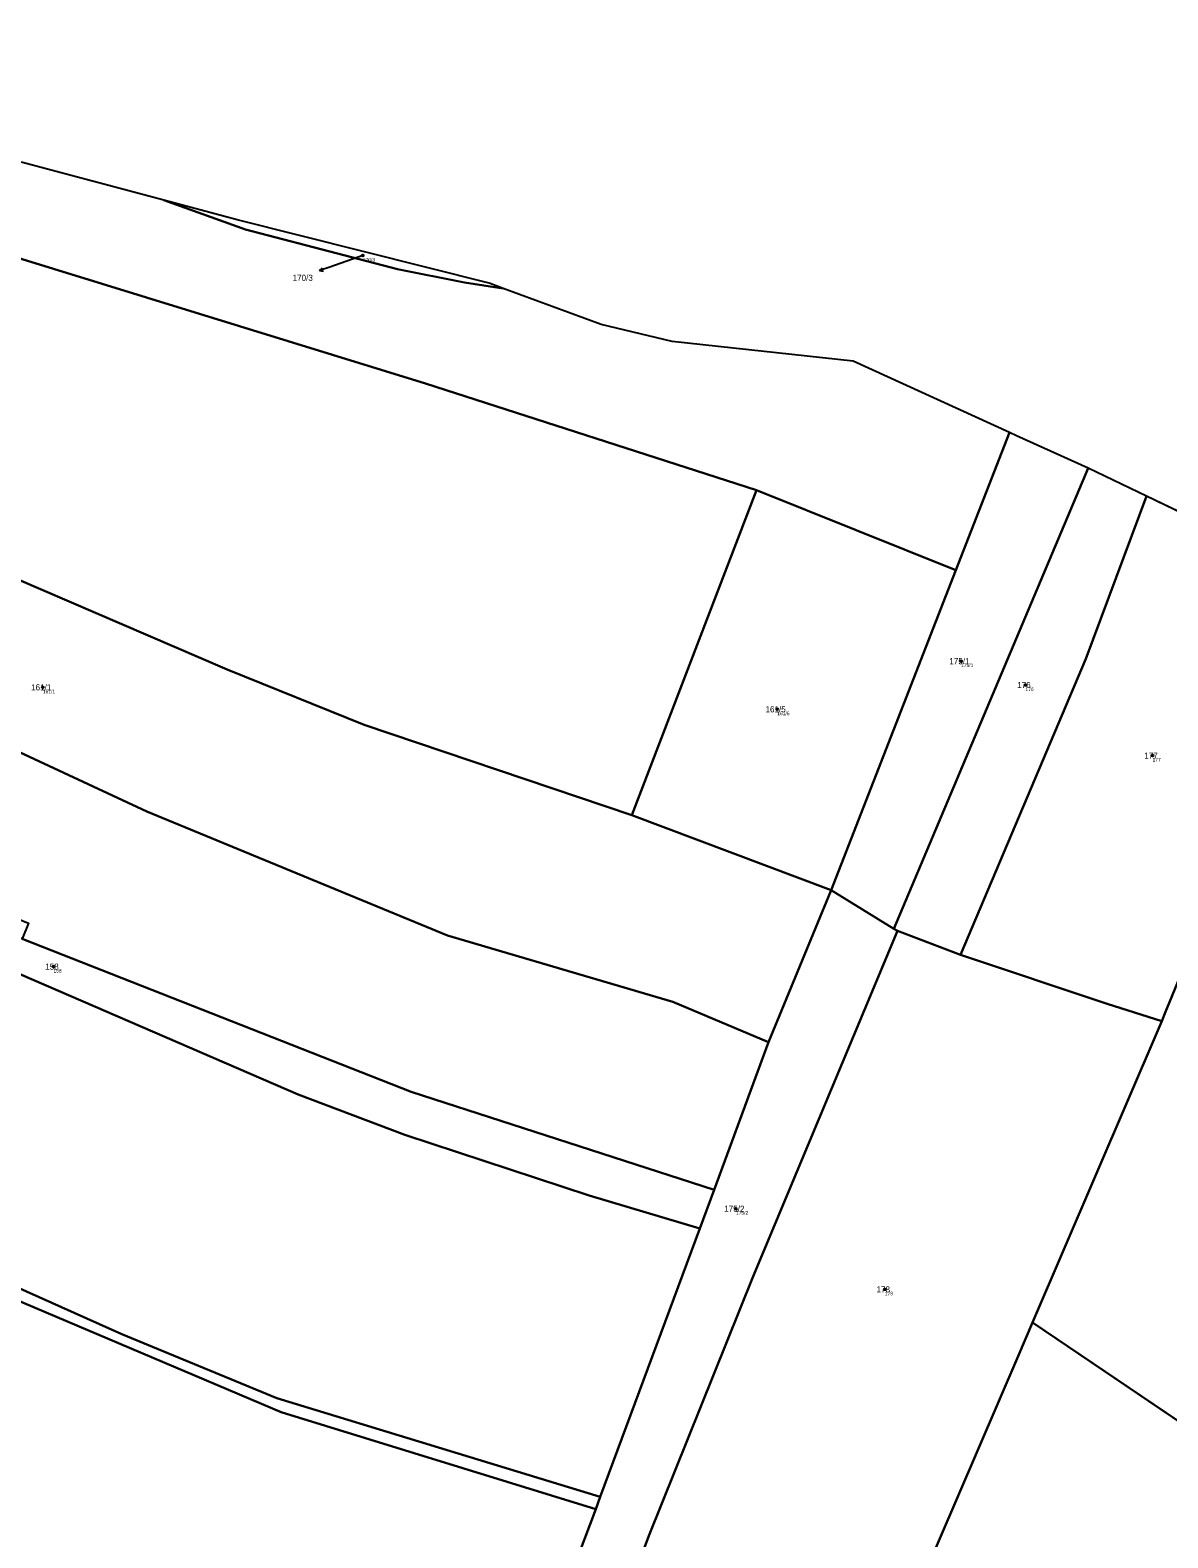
# Model space of a CAD drawing. Extents: x -700238 to -698499, y -1070626 to -1068006.
# Drawn here: x -699815.7 to -699496.9, y -1068498.7 to -1068076.1 of the extents above; entities that cross this region are included whole.
import ezdxf

# ---------------------------------------------------------------- set-up
doc = ezdxf.new("R2010")
doc.units = 0
for name, color, linetype in [('Definiční body', 7, 'Continuous'), ('Hranice parcel', 7, 'Continuous'), ('Parcelní čísla', 7, 'Continuous'), ('Polygon ku', 7, 'Continuous'), ('Polygon parcely', 7, 'Continuous'), ('Pop  PČ popisy', 7, 'Continuous')]:
    doc.layers.add(name, color=color, linetype=linetype)

msp = doc.modelspace()

# ---------------------------------------------------------------- linework, layer by layer
at = {"layer": 'Definiční body'}
for centre in [(-699722.47, -1068139.24994), (-699554.81, -1068252.94994), (-699812.13, -1068260.27994), (-699536.76, -1068259.63994), (-699606.32, -1068266.42994), (-699501.14, -1068279.40994), (-699809.15, -1068338.55994), (-699617.89, -1068406.41994), (-699576.18, -1068429.02994)]:
    msp.add_circle(centre, 0.25, dxfattribs=at)
at = {"layer": 'Hranice parcel'}
for p, q in [((-699778.25, -1068123.74), (-699818.2, -1068113.11)), ((-699757.69, -1068129.21), (-699778.25, -1068123.74)), ((-699687.02, -1068147.03), (-699757.69, -1068129.21)), ((-699683.1, -1068148.48), (-699687.02, -1068147.03)), ((-699655.7, -1068158.62), (-699683.1, -1068148.48)), ((-699635.75, -1068163.34), (-699655.7, -1068158.62)), ((-699585.07, -1068168.88), (-699635.75, -1068163.34)), ((-699541.2, -1068188.84), (-699585.07, -1068168.88)), ((-699556.25, -1068227.41), (-699541.2, -1068188.84)), ((-699539.23, -1068189.74), (-699541.2, -1068188.84)), ((-699519.18, -1068198.86), (-699539.23, -1068189.74)), ((-699573.62, -1068327.95), (-699519.18, -1068198.86)), ((-699502.86, -1068206.71), (-699519.18, -1068198.86)), ((-699647.05, -1068296.11), (-699612.1, -1068205.01)), ((-699556.25, -1068227.41), (-699612.1, -1068205.01)), ((-699468.76, -1068223.11), (-699502.86, -1068206.71)), ((-699591.24, -1068317.17), (-699556.25, -1068227.41)), ((-699591.24, -1068317.17), (-699647.05, -1068296.11)), ((-699608.73, -1068359.75), (-699591.24, -1068317.17)), ((-699591.24, -1068317.17), (-699573.62, -1068327.95)), ((-699572.66, -1068328.54), (-699573.62, -1068327.95)), ((-699572.66, -1068328.54), (-699554.94, -1068335.25)), ((-699499.35, -1068355.82), (-699534.75, -1068438.26)), ((-699498.53, -1068353.82), (-699499.35, -1068355.82)), ((-699623.95, -1068401.12), (-699608.73, -1068359.75)), ((-699627.99, -1068411.98), (-699623.95, -1068401.12)), ((-699655.97, -1068487.17), (-699627.99, -1068411.98)), ((-699534.75, -1068438.26), (-699459.74, -1068489.07)), ((-699657.18, -1068490.6), (-699655.97, -1068487.17)), ((-699671.14, -1068527.69), (-699657.18, -1068490.6))]:
    msp.add_line(p, q, dxfattribs=at)
for points in [[(-699612.1, -1068205.01), (-699704.91, -1068175.15), (-699847.75, -1068131.11), (-699903.56, -1068111.83), (-699936.42, -1068098.78), (-699978.4, -1068088.46), (-699998.31, -1068082.9)], [(-699647.05, -1068296.11), (-699722.11, -1068270.77), (-699760.47, -1068255.26), (-699834.34, -1068223.51), (-699836.42, -1068229.4), (-699946.86, -1068177.24), (-700044.14, -1068129.31), (-700087.38, -1068111.39)], [(-699778.25, -1068123.74), (-699755.33, -1068131.92), (-699712.7, -1068143.08), (-699693.92, -1068146.8), (-699683.1, -1068148.48)], [(-700091.82, -1068153.6), (-699982.79, -1068203.82), (-699863.89, -1068257.44), (-699783, -1068295.12), (-699698.72, -1068329.85), (-699635.57, -1068348.43), (-699608.73, -1068359.75)], [(-699554.94, -1068335.25), (-699519.85, -1068252.28), (-699502.86, -1068206.71)], [(-699627.99, -1068411.98), (-699659.02, -1068402.7), (-699710.69, -1068385.66), (-699740.56, -1068374.38), (-699875.66, -1068316.05), (-699927.93, -1068294.45), (-700000.63, -1068259.75), (-700062.96, -1068229.76), (-700089.79, -1068219.21)], [(-699446.94, -1068230.19), (-699466.45, -1068275.29), (-699484.18, -1068318.68), (-699496.38, -1068348.56), (-699497.48, -1068351.24), (-699498.53, -1068353.82)], [(-699623.95, -1068401.12), (-699708.94, -1068373.65), (-699817.93, -1068330.74)], [(-699655.01, -1068532.14), (-699642.31, -1068498.14), (-699613.14, -1068425.59), (-699572.66, -1068328.54)], [(-699554.94, -1068335.25), (-699513.83, -1068348.95), (-699498.53, -1068353.82)], [(-699655.97, -1068487.17), (-699746.59, -1068459.53), (-699790, -1068441.55), (-699866.66, -1068407.29), (-699955.8, -1068368.76), (-700005.69, -1068352.12), (-700047.78, -1068341.46)], [(-699657.18, -1068490.6), (-699745.37, -1068463.45), (-699826.68, -1068428.95), (-699890.63, -1068400.44), (-699955.93, -1068372.18), (-700009.61, -1068354.69), (-700046.18, -1068345.86)], [(-699583.54, -1068551.89), (-699538.81, -1068447.71), (-699534.75, -1068438.26)]]:
    msp.add_lwpolyline(points, dxfattribs=at)
at = {"layer": 'Polygon ku'}
for points in [[(-699468.76, -1068223.11), (-699502.86, -1068206.71), (-699519.18, -1068198.86), (-699539.23, -1068189.74), (-699541.2, -1068188.84), (-699585.07, -1068168.88), (-699635.75, -1068163.34), (-699655.7, -1068158.62), (-699683.1, -1068148.48), (-699687.02, -1068147.03), (-699757.69, -1068129.21), (-699778.25, -1068123.74), (-699818.2, -1068113.11)], [(-699459.74, -1068489.07), (-699534.75, -1068438.26), (-699499.35, -1068355.82), (-699498.53, -1068353.82), (-699497.48, -1068351.24), (-699496.38, -1068348.56)]]:
    msp.add_lwpolyline(points, dxfattribs=at)
at = {"layer": 'Polygon parcely'}
for points in [[(-699847.75, -1068131.11), (-699903.56, -1068111.83), (-699936.42, -1068098.78), (-699978.4, -1068088.46), (-699998.31, -1068082.9), (-699998.06, -1068112.08), (-700082.81, -1068076.08), (-700090.39, -1068110.64), (-700087.38, -1068111.39), (-700044.14, -1068129.31), (-699946.86, -1068177.24), (-699836.42, -1068229.4), (-699834.34, -1068223.51), (-699760.47, -1068255.26), (-699722.11, -1068270.77), (-699647.05, -1068296.11), (-699612.1, -1068205.01), (-699704.91, -1068175.15)], [(-699591.24, -1068317.17), (-699647.05, -1068296.11), (-699722.11, -1068270.77), (-699760.47, -1068255.26), (-699834.34, -1068223.51), (-699836.42, -1068229.4), (-699946.86, -1068177.24), (-700044.14, -1068129.31), (-700087.38, -1068111.39), (-700089.86, -1068130.36), (-700090.77, -1068136.56), (-700089.78, -1068150.52), (-700091.82, -1068153.6), (-699982.79, -1068203.82), (-699863.89, -1068257.44), (-699783, -1068295.12), (-699698.72, -1068329.85), (-699635.57, -1068348.43), (-699608.73, -1068359.75)], [(-699712.7, -1068143.08), (-699693.92, -1068146.8), (-699683.1, -1068148.48), (-699687.02, -1068147.03), (-699757.69, -1068129.21), (-699778.25, -1068123.74), (-699755.33, -1068131.92)], [(-699881.04, -1068299.73), (-699816.11, -1068326.4), (-699817.93, -1068330.74), (-699708.94, -1068373.65), (-699623.95, -1068401.12), (-699608.73, -1068359.75), (-699635.57, -1068348.43), (-699698.72, -1068329.85), (-699783, -1068295.12), (-699863.89, -1068257.44), (-699982.79, -1068203.82), (-700091.82, -1068153.6), (-700093.72, -1068156.82), (-700098.76, -1068159.5), (-700092.58, -1068198.68), (-699982.77, -1068250.43)], [(-699519.18, -1068198.86), (-699539.23, -1068189.74), (-699541.2, -1068188.84), (-699556.25, -1068227.41), (-699591.24, -1068317.17), (-699573.62, -1068327.95)], [(-699572.66, -1068328.54), (-699554.94, -1068335.25), (-699519.85, -1068252.28), (-699502.86, -1068206.71), (-699519.18, -1068198.86), (-699573.62, -1068327.95)], [(-699708.94, -1068373.65), (-699817.93, -1068330.74), (-699901.99, -1068293.89), (-700054.94, -1068220), (-700092.18, -1068203.16), (-700089.79, -1068219.21), (-700062.96, -1068229.76), (-700000.63, -1068259.75), (-699927.93, -1068294.45), (-699875.66, -1068316.05), (-699740.56, -1068374.38), (-699710.69, -1068385.66), (-699659.02, -1068402.7), (-699627.99, -1068411.98), (-699623.95, -1068401.12)], [(-699612.1, -1068205.01), (-699647.05, -1068296.11), (-699591.24, -1068317.17), (-699556.25, -1068227.41)], [(-699468.76, -1068223.11), (-699502.86, -1068206.71), (-699519.85, -1068252.28), (-699554.94, -1068335.25), (-699513.83, -1068348.95), (-699498.53, -1068353.82), (-699497.48, -1068351.24), (-699496.38, -1068348.56), (-699484.18, -1068318.68), (-699466.45, -1068275.29), (-699446.94, -1068230.19)], [(-700000.63, -1068259.75), (-700062.96, -1068229.76), (-700089.79, -1068219.21), (-700079.51, -1068265.19), (-700047.78, -1068341.46), (-700005.69, -1068352.12), (-699955.8, -1068368.76), (-699866.66, -1068407.29), (-699790, -1068441.55), (-699746.59, -1068459.53), (-699655.97, -1068487.17), (-699627.99, -1068411.98), (-699659.02, -1068402.7), (-699710.69, -1068385.66), (-699740.56, -1068374.38), (-699875.66, -1068316.05), (-699927.93, -1068294.45)], [(-699572.66, -1068328.54), (-699573.62, -1068327.95), (-699591.24, -1068317.17), (-699608.73, -1068359.75), (-699623.95, -1068401.12), (-699627.99, -1068411.98), (-699655.97, -1068487.17), (-699657.18, -1068490.6), (-699671.14, -1068527.69), (-699655.01, -1068532.14), (-699642.31, -1068498.14), (-699613.14, -1068425.59)], [(-699655.01, -1068532.14), (-699584.32, -1068553.61), (-699583.54, -1068551.89), (-699538.81, -1068447.71), (-699534.75, -1068438.26), (-699499.35, -1068355.82), (-699498.53, -1068353.82), (-699513.83, -1068348.95), (-699554.94, -1068335.25), (-699572.66, -1068328.54), (-699613.14, -1068425.59), (-699642.31, -1068498.14)], [(-700047.78, -1068341.46), (-700046.18, -1068345.86), (-700009.61, -1068354.69), (-699955.93, -1068372.18), (-699890.63, -1068400.44), (-699826.68, -1068428.95), (-699745.37, -1068463.45), (-699657.18, -1068490.6), (-699655.97, -1068487.17), (-699746.59, -1068459.53), (-699790, -1068441.55), (-699866.66, -1068407.29), (-699955.8, -1068368.76), (-700005.69, -1068352.12)], [(-699955.93, -1068372.18), (-700009.61, -1068354.69), (-700046.18, -1068345.86), (-700040.87, -1068359.92), (-700034.51, -1068382.29), (-700033.18, -1068393.26), (-700008.42, -1068397.14), (-699968.89, -1068409.59), (-699915.7, -1068430.51), (-699875.35, -1068449.22), (-699911.29, -1068553.85), (-699895.28, -1068555.81), (-699839.16, -1068564.86), (-699779.49, -1068577.34), (-699695.89, -1068598.19), (-699684.13, -1068602.07), (-699680.08, -1068567.69), (-699671.14, -1068527.69), (-699657.18, -1068490.6), (-699745.37, -1068463.45), (-699826.68, -1068428.95), (-699890.63, -1068400.44)], [(-699459.74, -1068489.07), (-699534.75, -1068438.26), (-699538.81, -1068447.71), (-699583.54, -1068551.89), (-699545.8, -1068564.77), (-699514.72, -1068578.68), (-699489.31, -1068592.29), (-699448.71, -1068496.54)]]:
    msp.add_lwpolyline(points, close=True, dxfattribs=at)
msp.add_lwpolyline([(-699847.75, -1068131.11), (-699704.91, -1068175.15), (-699612.1, -1068205.01), (-699556.25, -1068227.41), (-699541.2, -1068188.84), (-699585.07, -1068168.88), (-699635.75, -1068163.34), (-699655.7, -1068158.62), (-699683.1, -1068148.48), (-699693.92, -1068146.8), (-699712.7, -1068143.08), (-699755.33, -1068131.92), (-699778.25, -1068123.74), (-699818.2, -1068113.11)], dxfattribs=at)
at = {"layer": 'Pop  PČ popisy'}
for p, q in [((-699722.47, -1068139.25), (-699731.72, -1068142.49)), ((-699731.72, -1068142.49), (-699734.557, -1068143.467)), ((-699734.557, -1068143.467), (-699733.774, -1068142.668)), ((-699734.557, -1068143.467), (-699733.448, -1068143.614))]:
    msp.add_line(p, q, dxfattribs=at)

# ---------------------------------------------------------------- texts
at = {"layer": 'Definiční body'}
for s, p in [('170/3', (-699722.47, -1068140.906)), ('175/1', (-699554.81, -1068254.606)), ('161/1', (-699812.13, -1068261.936)), ('176', (-699536.76, -1068261.296)), ('161/5', (-699606.32, -1068268.086)), ('177', (-699501.14, -1068281.066)), ('158', (-699809.15, -1068340.216)), ('175/2', (-699617.89, -1068408.076)), ('178', (-699576.18, -1068430.686))]:
    msp.add_text(s, height=0.999996, dxfattribs=at).set_placement(p)
at = {"layer": 'Parcelní čísla'}
for s, p in [('170/3', (-699742.147, -1068146.328)), ('175/1', (-699558.108, -1068253.8)), ('176', (-699539.085, -1068260.489)), ('161/1', (-699815.428, -1068261.13)), ('161/5', (-699609.618, -1068267.279)), ('177', (-699503.465, -1068280.259)), ('158', (-699811.475, -1068339.41)), ('175/2', (-699621.188, -1068407.269)), ('178', (-699578.505, -1068429.88))]:
    msp.add_text(s, height=1.699998, dxfattribs=at).set_placement(p)

doc.saveas('drawing.dxf')
